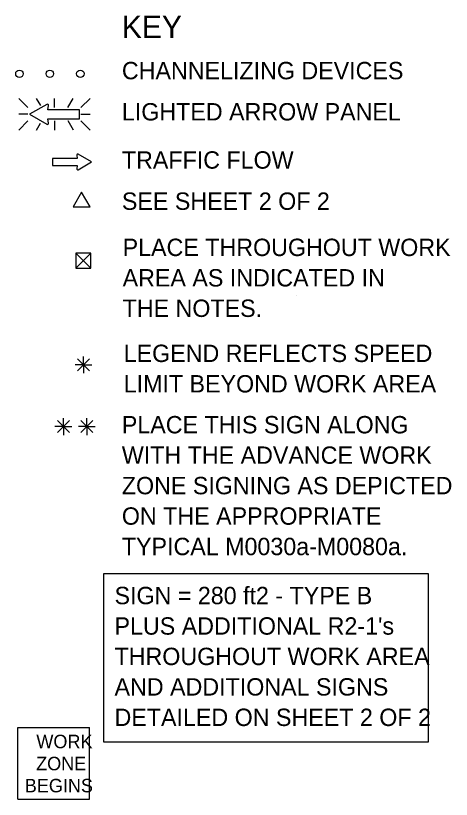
# Model space of a CAD drawing. Extents: x 16303 to 18479, y 5704 to 6974.
# Drawn here: x 17196.1 to 17429.2, y 6502.7 to 6922.2 of the extents above; entities that cross this region are included whole.
import ezdxf

# ---------------------------------------------------------------- set-up
doc = ezdxf.new("R2010")
doc.units = 0
for name, color, linetype in [('MT_SCRATCH_LEVEL_E', 7, 'Continuous'), ('TRAFFIC_SIGNS_PR', 7, 'Continuous'), ('TYPICAL_TEXT_DIMEN_EX', 7, 'Continuous'), ('TYPICAL_TEXT_DIMEN_PR', 7, 'Continuous')]:
    doc.layers.add(name, color=color, linetype=linetype)

msp = doc.modelspace()

# ---------------------------------------------------------------- linework, layer by layer
at = {"layer": 'MT_SCRATCH_LEVEL_E'}
for p, q in [((17228.75, 6847.56), (17229.06, 6845.79)), ((17236.67, 6843.94), (17229.44, 6848.05)), ((17229.06, 6845.79), (17215.81, 6845.79)), ((17215.81, 6845.79), (17215.81, 6842.05)), ((17229.44, 6839.79), (17236.67, 6843.94)), ((17215.81, 6842.05), (17229.06, 6842.05)), ((17229.06, 6842.05), (17228.75, 6840.27))]:
    msp.add_line(p, q, dxfattribs=at)
for centre, start, end in [((17229.21, 6847.64), 60.4248, 189.9638), ((17229.21, 6840.2), 170.0362, 299.7731)]:
    msp.add_arc(centre, 0.463, start, end, dxfattribs=at)
at = {"layer": 'TRAFFIC_SIGNS_PR'}
for p, q in [((17197.74, 6877.94), (17202.67, 6873.01)), ((17209.5, 6874.12), (17207.3, 6877.94)), ((17216.82, 6873.01), (17216.82, 6877.94)), ((17224.06, 6873.01), (17226.91, 6877.94)), ((17230.97, 6873.01), (17235.91, 6877.95)), ((17202.67, 6869.45), (17197.74, 6869.45)), ((17230.97, 6869.45), (17235.91, 6869.45)), ((17197.74, 6860.97), (17202.67, 6865.9)), ((17207.25, 6860.96), (17209.37, 6864.63)), ((17216.82, 6865.9), (17216.82, 6860.96)), ((17226.95, 6860.96), (17224.1, 6865.9)), ((17230.97, 6865.9), (17235.91, 6860.96)), ((17197.15, 6502.73), (17197.15, 6541.13)), ((17197.15, 6541.13), (17235.55, 6541.13)), ((17235.55, 6502.73), (17235.55, 6541.13)), ((17197.15, 6502.73), (17235.55, 6502.73))]:
    msp.add_line(p, q, dxfattribs=at)
for points in [[(17212.75, 6874.73), (17203.46, 6869.45), (17212.75, 6864.13)], [(17213.63, 6864.76), (17213.22, 6867.03), (17230.24, 6867.03), (17230.24, 6871.83), (17213.22, 6871.83), (17213.63, 6874.11)]]:
    msp.add_lwpolyline(points, dxfattribs=at)
for centre in [(17198.08, 6891.14), (17214.38, 6891.14), (17230.68, 6891.14)]:
    msp.add_circle(centre, 2, dxfattribs=at)
for centre, radius, start, end in [((17213.04, 6874.21), 0.598, 350.7308, 118.8916), ((17213.04, 6864.66), 0.597, 241.4833, 9.9593)]:
    msp.add_arc(centre, radius, start, end, dxfattribs=at)
at = {"layer": 'TYPICAL_TEXT_DIMEN_EX'}
msp.add_lwpolyline([(17243.21, 6623.6), (17416.86, 6623.6), (17416.86, 6533.27), (17243.21, 6533.27)], close=True, dxfattribs=at)
at = {"layer": 'TYPICAL_TEXT_DIMEN_PR'}
for p, q in [((17228.3, 6795.07), (17236.3, 6787.07)), ((17228.3, 6787.07), (17236.3, 6795.07)), ((17229.24, 6738.49), (17235.62, 6732.11)), ((17235.62, 6738.49), (17229.24, 6732.11)), ((17232.43, 6735.3), (17232.43, 6739.76)), ((17232.43, 6735.3), (17227.9, 6735.3)), ((17232.43, 6735.3), (17235.62, 6735.3)), ((17232.43, 6735.3), (17236.91, 6735.3)), ((17232.43, 6735.3), (17232.43, 6730.8)), ((17218.47, 6705.44), (17224.84, 6699.06)), ((17224.84, 6705.44), (17218.47, 6699.06)), ((17221.65, 6702.25), (17221.65, 6706.71)), ((17231.02, 6705.44), (17237.4, 6699.06)), ((17237.4, 6705.44), (17231.02, 6699.06)), ((17234.21, 6702.25), (17234.21, 6706.71)), ((17221.65, 6702.25), (17217.12, 6702.25)), ((17221.65, 6702.25), (17224.84, 6702.25)), ((17221.65, 6702.25), (17226.13, 6702.25)), ((17221.65, 6702.25), (17221.65, 6697.75)), ((17234.21, 6702.25), (17229.68, 6702.25)), ((17234.21, 6702.25), (17237.4, 6702.25)), ((17234.21, 6702.25), (17238.69, 6702.25)), ((17234.21, 6702.25), (17234.21, 6697.75))]:
    msp.add_line(p, q, dxfattribs=at)
for points in [[(17231.39, 6827.76), (17226.86, 6819.93), (17235.91, 6819.93)], [(17228.3, 6795.07), (17228.3, 6787.07), (17236.3, 6787.07), (17236.3, 6795.07)]]:
    msp.add_lwpolyline(points, close=True, dxfattribs=at)
msp.add_open_spline([(17346.31, 6772.35), (17346.33, 6772.35), (17346.33, 6772.35), (17346.33, 6772.35)], degree=2, dxfattribs=at)

# ---------------------------------------------------------------- texts
at = {"layer": 'TRAFFIC_SIGNS_PR'}
for s, height, p in [('PLACE THROUGHOUT WORK', 9.3, (17253.31, 6793.57)), ('AREA AS INDICATED IN', 9.3, (17253.31, 6777.27)), ('THE NOTES.', 9.3, (17253.31, 6760.97)), ('PLACE THIS SIGN ALONG', 9.3, (17252.89, 6698.63)), ('WITH THE ADVANCE WORK', 9.3, (17252.89, 6682.33)), ('ZONE SIGNING AS DEPICTED', 9.3, (17252.89, 6666.03)), ('ON THE APPROPRIATE', 9.3, (17252.89, 6649.73)), ('TYPICAL M0030a-M0080a.', 9.3, (17252.89, 6633.43)), ('WORK', 7.217, (17207.15, 6530.09)), ('ZONE', 7.217, (17207.03, 6518.28)), ('BEGINS', 7.217, (17200.96, 6506.47))]:
    msp.add_text(s, height=height, dxfattribs=at).set_placement(p)
at = {"layer": 'TYPICAL_TEXT_DIMEN_EX'}
for s, height, p in [('KEY', 12, (17252.92, 6910.25)), ('CHANNELIZING DEVICES', 9.3, (17252.92, 6888.2)), ('LIGHTED ARROW PANEL', 9.3, (17252.92, 6866.15)), ('TRAFFIC FLOW', 9.3, (17252.92, 6840.35)), ('SEE SHEET 2 OF 2', 9.3, (17252.92, 6818.3)), ('LEGEND REFLECTS SPEED', 9.3, (17253.88, 6736.83)), ('LIMIT BEYOND WORK AREA', 9.3, (17253.88, 6720.53)), ('SIGN = 280 ft2 - TYPE B', 9.3, (17248.98, 6607.18)), ("PLUS ADDITIONAL R2-1's", 9.3, (17248.98, 6590.88)), ('THROUGHOUT WORK AREA', 9.3, (17248.98, 6574.58)), ('AND ADDITIONAL SIGNS', 9.3, (17248.98, 6558.28)), ('DETAILED ON SHEET 2 OF 2', 9.3, (17248.98, 6541.98))]:
    msp.add_text(s, height=height, dxfattribs=at).set_placement(p)

doc.saveas('drawing.dxf')
